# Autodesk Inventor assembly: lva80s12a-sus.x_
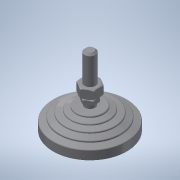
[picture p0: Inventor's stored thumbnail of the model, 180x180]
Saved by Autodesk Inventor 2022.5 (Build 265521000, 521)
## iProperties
Part Number: lva80s12a-sus.x_
Material: 一般
Document SubType Name: Assembly
Designer: ImaoCorp
Sending System: SOLIDWORKS 2017-2017317
MC: AMD64
MC_MODEL: Intel64 Family 6 Model 60 Stepping 3, GenuineIntel
OS: Windows_NT
FRU: Parasolid Version 29.0, build 201,  4-17-2017
FORMAT: text
GUISE: transmit
KEY: lva80s12a-sus
FILE: lva80s12a-sus.x_t
DATE: Mon Jul 01 18:09:41 2019
Author: ImaoCorp
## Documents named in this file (3)
- X:\14_SW2022-Inv2022\00_全2023-1023新製品(TCC)まで\l\lva80s12a-sus\LVA80S12A-SUS.iam
- X:\14_SW2022-Inv2022\00_全2023-1023新製品(TCC)まで\l\lva80s12a-sus\lva80s12a-sus_01.ipt
- X:\14_SW2022-Inv2022\00_全2023-1023新製品(TCC)まで\l\lva80s12a-sus\lva80s12a-sus_02.ipt
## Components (2 placed, 2 different names)
1. lva80s12a-sus_01
2. lva80s12a-sus_02
